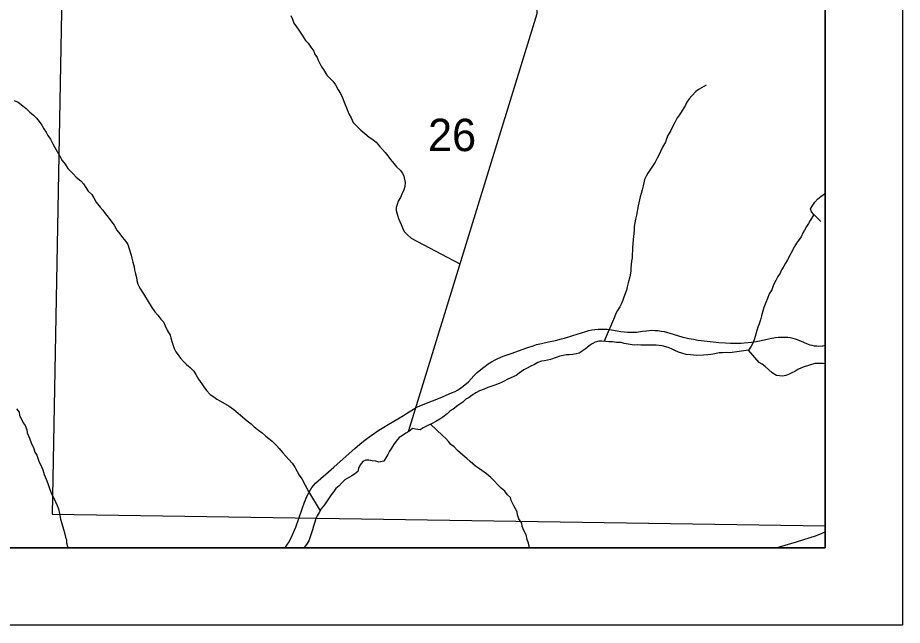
# Model space of a CAD drawing. Extents: x 0 to 34, y -8.9 to 22.
# Drawn here: x 29.472 to 30.617, y 7.004 to 7.79 of the extents above; entities that cross this region are included whole.
import ezdxf

# ---------------------------------------------------------------- set-up
doc = ezdxf.new("R2010")
doc.units = 0
for name, color, linetype in [('GM_X_Corporation', 7, 'Continuous'), ('GM_X_Minor_River', 7, 'Continuous'), ('GM_X_Section_Text', 7, 'Continuous'), ('GM_X_Township_Road', 7, 'Continuous'), ('SH_Data', 7, 'Continuous')]:
    doc.layers.add(name, color=color, linetype=linetype)

msp = doc.modelspace()

# ---------------------------------------------------------------- linework, layer by layer
at = {"layer": 'GM_X_Corporation'}
for points in [[(28.7046, 7.104), (30.5167, 7.104), (30.5167, 13.904), (28.8143, 13.904), (28.8122, 13.7561), (28.8049, 13.053), (28.7787, 12.0377), (28.7786, 12.0342), (28.7779, 11.9899), (28.7762, 11.8872), (28.7797, 11.7437), (28.7775, 11.7346), (28.7754, 11.6346), (28.7651, 11.3014), (28.7622, 11.1187), (28.7609, 11.0119), (28.7377, 10.2012), (28.7308, 9.4444), (28.7238, 9.1729), (28.7123, 8.2818)], [(28.7046, 7.104), (30.5167, 7.104), (30.5167, 12.0118), (29.364, 12.0313), (29.2718, 12.0324), (28.9225, 12.0359), (28.8128, 12.0371), (28.7787, 12.0377), (28.7786, 12.0342), (28.7779, 11.9899), (28.7762, 11.8872), (28.7797, 11.7437), (28.7775, 11.7346), (28.7754, 11.6346), (28.7651, 11.3014), (28.7622, 11.1187), (28.7609, 11.0119), (28.7377, 10.2012), (28.7308, 9.4444), (28.7238, 9.1729), (28.7123, 8.2818)], [(30.5167, 7.1326), (30.5167, 8.1537), (29.5357, 8.1691), (29.5168, 7.1478)]]:
    msp.add_lwpolyline(points, close=True, dxfattribs=at)
at = {"layer": 'GM_X_Minor_River'}
for points in [[(30.1733, 7.8598), (30.1677, 7.8547), (30.1636, 7.8505), (30.1592, 7.8447), (30.1555, 7.8397), (30.1521, 7.834), (30.1503, 7.8302), (30.1485, 7.8244), (30.1464, 7.8191), (30.1457, 7.8138), (30.1447, 7.8073), (30.1444, 7.8035), (30.144, 7.7994), (30.1438, 7.7944), (29.9774, 7.2542)], [(29.8256, 7.7926), (29.8275, 7.7877), (29.8295, 7.7824), (29.833, 7.7776), (29.8357, 7.7734), (29.8404, 7.7671), (29.8447, 7.7603), (29.8481, 7.7566), (29.8516, 7.7514), (29.8555, 7.7465)], [(29.8555, 7.7465), (29.8563, 7.7427), (29.8598, 7.7382), (29.861, 7.7345), (29.8653, 7.7262), (29.868, 7.7225), (29.8723, 7.7153), (29.8758, 7.7116), (29.88, 7.7075), (29.8835, 7.7026), (29.8866, 7.6963), (29.8897, 7.6914), (29.8925, 7.6861), (29.8953, 7.6782), (29.8976, 7.6729), (29.9004, 7.6654), (29.9035, 7.6602), (29.9063, 7.6541), (29.9105, 7.6497), (29.9159, 7.6441), (29.9213, 7.64), (29.9267, 7.6352), (29.9305, 7.633), (29.9359, 7.6285), (29.9401, 7.6233), (29.944, 7.6192), (29.9474, 7.6154), (29.9509, 7.611), (29.9544, 7.6061), (29.9587, 7.6009), (29.9621, 7.5967), (29.9668, 7.5923), (29.9699, 7.5885), (29.9718, 7.5848), (29.9735, 7.5765), (29.9732, 7.5715), (29.9717, 7.567), (29.9692, 7.5616), (29.9674, 7.557), (29.9644, 7.5524), (29.963, 7.5482), (29.9619, 7.5441), (29.962, 7.5403), (29.9636, 7.5342), (29.9648, 7.5301), (29.9664, 7.5263), (29.9684, 7.5222), (29.9699, 7.518), (29.9723, 7.5132), (29.9765, 7.5087), (29.9812, 7.5046), (30.0443, 7.4714)], [(30.3629, 7.7024), (30.3539, 7.6973), (30.3494, 7.6942), (30.3442, 7.6884), (30.3409, 7.6846), (30.338, 7.6803), (30.3361, 7.6765), (30.3317, 7.6696), (30.3284, 7.6642), (30.3254, 7.66), (30.3225, 7.6539), (30.3196, 7.6493), (30.317, 7.6436), (30.3134, 7.6371), (30.3115, 7.6329), (30.3105, 7.6287), (30.3064, 7.6222), (30.3039, 7.6164), (30.302, 7.6126), (30.2995, 7.608), (30.2969, 7.6027), (30.2873, 7.5885), (30.2851, 7.5846), (30.2833, 7.5804), (30.2822, 7.5759), (30.2812, 7.5721), (30.2801, 7.5671), (30.2787, 7.5622), (30.2776, 7.558), (30.2748, 7.5465), (30.2728, 7.5344), (30.2713, 7.529), (30.2696, 7.5195), (30.2697, 7.5154), (30.2694, 7.5108), (30.2687, 7.5066), (30.2684, 7.5028), (30.2678, 7.4922), (30.2675, 7.4884), (30.2672, 7.4835), (30.2673, 7.4793), (30.2662, 7.4747), (30.2656, 7.4656), (30.2653, 7.4618), (30.2643, 7.4546), (30.2618, 7.4466), (30.2607, 7.4417), (30.2597, 7.4375), (30.2575, 7.4318), (30.2539, 7.4211), (30.251, 7.4157), (30.2484, 7.4111), (30.2462, 7.4073), (30.2444, 7.4023), (30.231, 7.3712)], [(29.4676, 7.6824), (29.4726, 7.6803), (29.4787, 7.6758), (29.4833, 7.6721), (29.4879, 7.6676), (29.4922, 7.6639), (29.4964, 7.6598), (29.4999, 7.6553), (29.5034, 7.6505), (29.5061, 7.646), (29.5092, 7.6415), (29.5112, 7.6373), (29.5146, 7.6325), (29.5178, 7.6265), (29.5201, 7.6216), (29.5268, 7.6107), (29.5299, 7.6051), (29.5334, 7.6002), (29.5372, 7.5946), (29.5438, 7.5879), (29.548, 7.5834), (29.5538, 7.5786), (29.5573, 7.5748), (29.5635, 7.5655), (29.5681, 7.561), (29.5708, 7.5569), (29.5736, 7.5512), (29.579, 7.5445), (29.5821, 7.5408), (29.5852, 7.5363), (29.589, 7.5318), (29.5941, 7.5251), (29.5968, 7.5213), (29.6003, 7.5149), (29.6042, 7.5101), (29.6077, 7.5056), (29.6119, 7.5004), (29.6146, 7.4962), (29.6166, 7.4906), (29.619, 7.4827), (29.6199, 7.4789), (29.6211, 7.4736), (29.6227, 7.4676), (29.6235, 7.4638)], [(30.5112, 7.5259), (30.5024, 7.535), (30.499, 7.5388), (30.4978, 7.5425), (30.5007, 7.5471), (30.5037, 7.5513), (30.5074, 7.5552), (30.5111, 7.5583), (30.516, 7.5618), (30.5167, 7.5624)], [(30.5024, 7.5351), (30.4976, 7.5274), (30.4954, 7.5235), (30.4928, 7.5197), (30.4903, 7.5151), (30.4881, 7.5113), (30.4859, 7.5063), (30.4822, 7.5017), (30.4796, 7.4979), (30.4774, 7.4936), (30.4723, 7.4848), (30.4682, 7.4764), (30.4657, 7.4722), (30.4635, 7.4684), (30.4605, 7.4634), (30.4587, 7.4592), (30.4558, 7.455), (30.4532, 7.45), (30.4499, 7.4443), (30.4477, 7.4378), (30.4444, 7.4324), (30.4422, 7.4267), (30.4401, 7.4213), (30.4375, 7.4148), (30.4357, 7.4087), (30.4347, 7.4042), (30.4333, 7.3988), (30.4315, 7.3939), (30.4296, 7.3893), (30.4286, 7.3851), (30.4265, 7.3775), (30.425, 7.3729), (30.4232, 7.3687), (30.421, 7.3649), (30.4177, 7.3599)], [(29.6235, 7.4638), (29.6247, 7.4585), (29.626, 7.4536), (29.6264, 7.4498), (29.6276, 7.4449), (29.63, 7.44), (29.6339, 7.434), (29.6362, 7.4303), (29.6456, 7.4149), (29.6494, 7.4093), (29.6533, 7.4052), (29.6575, 7.4), (29.6606, 7.3962), (29.663, 7.391), (29.6661, 7.3849), (29.6693, 7.3793), (29.6705, 7.3755), (29.6717, 7.371), (29.6729, 7.3669), (29.6745, 7.362), (29.6768, 7.3575), (29.6799, 7.3537), (29.683, 7.3496), (29.6865, 7.3451), (29.6907, 7.3414), (29.6953, 7.3373), (29.7, 7.3325), (29.7027, 7.3283), (29.7062, 7.3223), (29.7105, 7.3164), (29.7132, 7.3122), (29.7163, 7.3077), (29.7213, 7.3025), (29.7259, 7.2992), (29.7297, 7.2966), (29.7347, 7.2937), (29.7458, 7.2874), (29.7519, 7.283), (29.7573, 7.2781), (29.7634, 7.2729), (29.7692, 7.2685), (29.7742, 7.2644), (29.778, 7.2607), (29.7838, 7.2562), (29.7884, 7.2529), (29.7934, 7.2484), (29.7972, 7.2455), (29.8014, 7.2421), (29.8072, 7.2366), (29.8103, 7.2328), (29.8153, 7.2272), (29.823, 7.2183), (29.8273, 7.2138), (29.8308, 7.2085), (29.8362, 7.198), (29.8397, 7.1935), (29.8483, 7.177), (29.8635, 7.1519)], [(30.5167, 7.3421), (30.5141, 7.3423), (30.5095, 7.3426), (30.5039, 7.3425), (30.499, 7.3413), (30.4941, 7.3397), (30.4899, 7.3381), (30.4862, 7.3369), (30.4817, 7.3349), (30.4776, 7.3322), (30.4738, 7.3306), (30.4701, 7.3286), (30.4659, 7.327), (30.4618, 7.3262), (30.4576, 7.3265), (30.4538, 7.3272), (30.4485, 7.3305), (30.4392, 7.3387), (30.4354, 7.3416), (30.4316, 7.3439), (30.4177, 7.3599), (30.3935, 7.3564), (30.389, 7.3567), (30.3841, 7.3563), (30.3799, 7.3562), (30.3742, 7.355), (30.369, 7.3541), (30.3652, 7.3537), (30.3595, 7.3532), (30.3504, 7.353), (30.3425, 7.3536), (30.3372, 7.3543), (30.3315, 7.3557), (30.3273, 7.3572), (30.3223, 7.3594), (30.3181, 7.3616), (30.3136, 7.3634), (30.306, 7.3655), (30.298, 7.3661), (30.2878, 7.366), (30.2832, 7.3662), (30.2783, 7.3662), (30.2745, 7.3665), (30.2696, 7.3664), (30.2647, 7.3671), (30.2567, 7.3684), (30.2529, 7.3695), (30.2468, 7.3698), (30.2419, 7.3704), (30.237, 7.3707), (30.2332, 7.3711), (30.2279, 7.3713), (30.2241, 7.3713), (30.2192, 7.37), (30.2155, 7.3681), (30.2117, 7.3654), (30.2065, 7.3611), (30.2024, 7.3584), (30.1987, 7.356), (30.1945, 7.3548), (30.1904, 7.354), (30.1858, 7.3535), (30.1817, 7.3535), (30.1779, 7.353), (30.1734, 7.3518), (30.1689, 7.3502), (30.1613, 7.3478), (30.1538, 7.3461), (30.15, 7.3457), (30.1451, 7.3437), (30.141, 7.341), (30.1354, 7.3386), (30.1313, 7.3363), (30.1271, 7.3343), (30.1208, 7.33), (30.117, 7.3269), (30.1065, 7.3222), (30.1017, 7.3198)], [(30.1017, 7.3198), (30.0979, 7.3179), (30.093, 7.3159), (30.0893, 7.3143), (30.0806, 7.3115), (30.0757, 7.3095), (30.0697, 7.3071), (30.0656, 7.3052), (30.0603, 7.3017), (30.0562, 7.2986), (30.0521, 7.2962), (30.048, 7.2924), (30.0417, 7.2881), (30.0357, 7.2834), (30.0316, 7.2811), (30.0278, 7.2776), (30.0222, 7.2733), (30.0185, 7.2706), (30.0133, 7.2675), (30.0084, 7.2651), (30.0046, 7.2632), (30.0009, 7.2616), (29.9968, 7.2592), (29.993, 7.2569), (29.9869, 7.2575), (29.9828, 7.2586), (29.9783, 7.2547), (29.9742, 7.2524), (29.9701, 7.2493), (29.9659, 7.2469), (29.9619, 7.2423), (29.9585, 7.2373), (29.9556, 7.2331), (29.9534, 7.2293), (29.9512, 7.2247), (29.9486, 7.2205), (29.9457, 7.2163), (29.9396, 7.215), (29.9354, 7.2161), (29.9309, 7.2167), (29.9263, 7.2174), (29.9226, 7.2174), (29.9188, 7.2158), (29.9151, 7.2115), (29.9133, 7.2066), (29.9122, 7.2028), (29.9081, 7.1993), (29.9044, 7.1973), (29.8954, 7.1919), (29.8917, 7.1884), (29.8879, 7.1842), (29.8838, 7.1807), (29.8813, 7.1768), (29.8776, 7.1726), (29.8753, 7.1688), (29.8716, 7.1638), (29.8691, 7.1599), (29.865, 7.1546), (29.8624, 7.15), (29.8595, 7.1457), (29.8577, 7.1419), (29.8566, 7.1374), (29.8548, 7.132), (29.8534, 7.1274), (29.8516, 7.121), (29.8487, 7.1133), (29.8457, 7.1084), (29.8428, 7.1045), (29.8416, 7.104)], [(29.4707, 7.2841), (29.4742, 7.2796), (29.4747, 7.2758), (29.4794, 7.266), (29.4817, 7.2623), (29.4841, 7.2567), (29.4845, 7.2529), (29.4873, 7.2461), (29.4901, 7.2386), (29.4924, 7.2337), (29.4944, 7.228), (29.4968, 7.2239), (29.4999, 7.2149), (29.5023, 7.2111), (29.5046, 7.2051), (29.5066, 7.1991), (29.509, 7.193), (29.511, 7.1874), (29.513, 7.1821), (29.5158, 7.1742), (29.5189, 7.1686), (29.5209, 7.1637), (29.5232, 7.1588), (29.5248, 7.1546), (29.5261, 7.1486), (29.5277, 7.1414), (29.5317, 7.1271), (29.5338, 7.118), (29.5354, 7.1143), (29.5354, 7.1105), (29.5369, 7.104)], [(30.1342, 7.104), (30.1337, 7.1062), (30.1329, 7.11), (30.1313, 7.1149), (30.1301, 7.1209), (30.1273, 7.1258), (30.125, 7.1318), (30.1245, 7.136), (30.1206, 7.1416), (30.1187, 7.1469), (30.1182, 7.1507), (30.1139, 7.1586), (30.1108, 7.1653), (30.1099, 7.1691), (30.1057, 7.1728), (30.1026, 7.1773), (30.0976, 7.1814), (30.0938, 7.1851), (30.0884, 7.1911), (30.0845, 7.1952), (30.0788, 7.2), (30.0696, 7.2063), (30.0646, 7.2096), (30.0577, 7.2159), (30.0534, 7.2197), (30.0481, 7.2241), (30.0412, 7.2301), (30.0369, 7.2349), (30.0327, 7.2379), (30.0296, 7.2416), (30.0261, 7.2457), (30.0219, 7.2494), (30.0061, 7.2639)]]:
    msp.add_lwpolyline(points, dxfattribs=at)
at = {"layer": 'GM_X_Township_Road'}
for points in [[(29.8182, 7.104), (29.8204, 7.1075), (29.8232, 7.1121), (29.8274, 7.1201), (29.8304, 7.1268), (29.832, 7.1308), (29.8401, 7.1546), (29.8432, 7.163), (29.8468, 7.1712), (29.8509, 7.1791), (29.8527, 7.182), (29.8552, 7.1853), (29.8575, 7.1879), (29.881, 7.2085), (29.9087, 7.2331), (29.9172, 7.2404), (29.9211, 7.2432), (29.9295, 7.2494), (29.9393, 7.2561), (29.9459, 7.2602), (29.9516, 7.2637), (29.9638, 7.2708), (29.9712, 7.2751), (29.9753, 7.2778), (29.9843, 7.2836), (29.9869, 7.2852), (29.9896, 7.2865), (29.9967, 7.2897), (30.0208, 7.299), (30.0267, 7.3015), (30.0335, 7.3044), (30.0381, 7.3064), (30.0411, 7.3081), (30.0439, 7.3098), (30.0469, 7.3118), (30.0508, 7.315), (30.0554, 7.319), (30.0623, 7.3265), (30.0668, 7.3308), (30.0714, 7.3349), (30.0752, 7.3379), (30.0808, 7.3419), (30.0852, 7.3446), (30.0901, 7.3473), (30.0933, 7.3488), (30.1003, 7.3518), (30.1104, 7.3554), (30.1309, 7.3627), (30.1391, 7.3655), (30.1436, 7.3669), (30.1497, 7.3684), (30.1591, 7.3705), (30.1678, 7.3724), (30.1757, 7.3743), (30.1795, 7.3752), (30.1863, 7.3772), (30.1903, 7.3785), (30.2072, 7.384), (30.2109, 7.385), (30.2148, 7.3859), (30.2188, 7.3865), (30.2233, 7.3869), (30.2291, 7.387), (30.2347, 7.3867), (30.2403, 7.3859), (30.2479, 7.3846), (30.2527, 7.3839), (30.2572, 7.3833), (30.2613, 7.383), (30.2646, 7.3829), (30.2726, 7.3831), (30.2805, 7.3841), (30.2857, 7.3849), (30.2891, 7.3853), (30.2927, 7.3854), (30.2967, 7.3853), (30.3004, 7.385), (30.3046, 7.3845), (30.3087, 7.3837), (30.3201, 7.3803), (30.3326, 7.3766), (30.3369, 7.3755), (30.3405, 7.3749), (30.3464, 7.3738), (30.3527, 7.3728), (30.3604, 7.3718), (30.3719, 7.3706), (30.3793, 7.3698), (30.388, 7.3692), (30.3945, 7.3689), (30.4031, 7.3688), (30.408, 7.3688), (30.4119, 7.3691), (30.4172, 7.3697), (30.4217, 7.3702), (30.4277, 7.3711), (30.432, 7.372), (30.4458, 7.3749), (30.4528, 7.3762), (30.4561, 7.3765), (30.4597, 7.3767), (30.4687, 7.3764), (30.4714, 7.376), (30.4749, 7.3753), (30.4779, 7.3744), (30.4806, 7.3736), (30.4856, 7.3715), (30.4925, 7.3682), (30.4969, 7.3667), (30.4995, 7.3661), (30.5026, 7.3655), (30.5059, 7.3652), (30.5085, 7.3651), (30.5137, 7.3654), (30.5167, 7.366)], [(30.4532, 7.104), (30.4576, 7.1054), (30.4797, 7.1121), (30.4974, 7.1175), (30.5042, 7.1198), (30.5098, 7.1217), (30.5167, 7.1248)]]:
    msp.add_lwpolyline(points, dxfattribs=at)
at = {"layer": 'SH_Data'}
for points in [[(23.6167, 14.004), (30.6167, 14.004), (30.6167, 7.004), (23.6167, 7.004)], [(23.7167, 13.904), (30.5167, 13.904), (30.5167, 7.104), (23.7167, 7.104)]]:
    msp.add_lwpolyline(points, close=True, dxfattribs=at)

# ---------------------------------------------------------------- texts
at = {"layer": 'GM_X_Section_Text'}
msp.add_text('26', height=0.04186, rotation=0, dxfattribs=at).set_placement((30.003, 7.6171))

doc.saveas('drawing.dxf')
